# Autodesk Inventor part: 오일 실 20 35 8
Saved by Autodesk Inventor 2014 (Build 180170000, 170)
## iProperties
Created: 2025-09
Part Number: 오일 실 20 35 8
Material: 일반
Document SubType Name: Modeling
Designer: dg
Density: 1 g/cm^3
Appearance: 기본값
Author: dg
Author: jhkim
Description: 오일-실
Creation Date: 2025-09-02
Sending System: Autodesk Inventor 2026
Preprocessor: ST-DEVELOPER v20.1
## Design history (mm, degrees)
node "오일 실 20 35 81"
body "Solid1"
node "기준1"
